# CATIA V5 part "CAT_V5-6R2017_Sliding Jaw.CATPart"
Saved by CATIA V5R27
Part number: Sliding Jaw
Bounding box of the stored display mesh (mm): x -32 to 32, y -16 to 16, z -9 to 36
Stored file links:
  E:\_Deepak\2017_Deepak\CATIA\Resources\Tutorial Files\Tutorials\c16_catia_v5_6r2016_tut\Bench vice\CAT_V5-6R2016_Sliding Jaw.CATPart
  C:\Program Files\Dassault Systemes\B09\intel_a\reffiles\standard\MetricThickPitch.txt
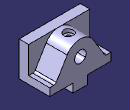
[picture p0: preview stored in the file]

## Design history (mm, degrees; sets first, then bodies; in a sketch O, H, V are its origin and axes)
Body1 (main body)
  Sketch1 on xy-plane, origin (0, 0, 0), H (1, 0, 0), V (0, 1, 0)
    line L1 (-32, -16) -> (32, -16)
    line L2 (32, -16) -> (32, 16)
    line L3 (32, 16) -> (-32, 16)
    line L4 (-32, 16) -> (-32, -16)
    distance H L1 = 16
    distance V L4 = 32
    length L4 = 32
    length L1 = 64
    horizontal: L1 H, L3 H
    vertical: L2 V, L4 V
  Pad1: profile Sketch1, direction (0, 0, 1), length 8
  Sketch2 on face of Pad1, origin (0, -16, 0), H (1, 0, 0), V (0, 0, 1)
    point P1 (-32, 0)
    line L1 (-32, 0) -> (32, 0)
    line L2 (32, 0) -> (32, 36)
    line L3 (32, 36) -> (-32, 36)
    line L4 (-32, 36) -> (-32, 0)
    reference projected line E1 (32, 0) -> (32, 8) from edge of Pad1
    reference projected line E2 (-32, 8) -> (-32, 0) from edge of Pad1
    length L2 = 36
    coincidence: P1 H, L2 E1, L4 E2
    horizontal: L1 H, L3 H
    vertical: L2 V, L4 V
  Pad2: profile Sketch2, direction (0, 1, 0), length 10
  Sketch3 on face of Pad1, origin (0, 16, 0), H (-1, 0, 0), V (0, 0, 1)
    arc A1 centre (0, 20) radius 16 from (13.6777, 28.3018) to (-13.6777, 28.3018) ccw
    point P1 (0, 20)
    reference projected line E1 (-32, 36) -> (32, 36) from edge of Pad2
    line L1 (-26, 8) -> (-13.6777, 28.3018)
    point P2 (-26, 8)
    line L2 (13.6777, 28.3018) -> (26, 8)
    point P3 (26, 8)
    reference projected line E2 (32, 8) -> (-32, 8) from edge of Pad1
    reference projected line E3 (32, 8) -> (-32, 8) from edge of Pad1
    line L3 (-26, 8) -> (26, 8)
    radius A1 = 16
    length L3 = 52
    distance V P3 = 26
    coincidence: P1 V, E2 P2, E3 P3
    tangency: A1 E1, L2 A1, L1 A1
    horizontal: L3 H
  Pad3: profile Sketch3, direction (0, -1, 0), up to the existing solid (limit type 2)
  Fillet1: radius 3, on 2 edges
  Sketch4 on face of Pad1, origin (-2.6964, 16, 22.8197), H (1, 0, 0), V (0, 0, -1)
    point P1 (2.6964, 2.8197)
    reference projected arc E1 centre (2.6964, 2.8197) radius 16 from (-10.9814, -5.4821) to (16.3741, -5.4821) ccw from edge of Pad3
    concentricity: P1 E1
  Hole1: placed by Sketch4, at (0, 16, 20) direction (0, -1, 0), diameter 12, depth 22, V-bottom angle 120
  Sketch5 on face of Pad1, origin (0, 16, 0), H (-1, 0, 0), V (0, 0, 1)
    point P1 (-7.75, 0)
    line L1 (-7.75, 0) -> (7.75, 0)
    line L2 (7.75, 0) -> (7.75, -9)
    line L3 (7.75, -9) -> (-7.75, -9)
    line L4 (-7.75, -9) -> (-7.75, 0)
    distance V L2 = 7.75
    length L3 = 15.5
    length L4 = 9
    coincidence: P1 H
    horizontal: L1 H, L3 H
    vertical: L2 V, L4 V
  Pad4: profile Sketch5, direction (0, -1, 0), length 32
  Sketch6 on face of Pad4, origin (-0.598, -1.2346, -9), H (1, 0, 0), V (0, -1, 0)
    point P1 (0.598, -9.2346)
    reference projected line E1 (8.348, -17.2346) -> (-7.152, -17.2346) from edge of Pad4
    reference projected line E2 (8.348, 14.7654) -> (8.348, -17.2346) from edge of Pad4
    distance P1 E1 = 8
    distance P1 E2 = 7.75
  Hole2: placed by Sketch6, at (0, 8, -9) direction (0, 0, 1), diameter 5, depth 16, V-bottom angle 120, threaded, thread diameter 6, thread depth 16, pitch 1
  RectPattern1: of Hole2, direction 1 instances 2, spacing 16, along edge of Pad4 reversed
  Sketch7 on face of Pad2, origin (-19.6018, -13.7351, 36), H (1, 0, 0), V (0, 1, 0)
    point P1 (19.6018, 17.7351)
    reference intersected line E1 through (19.6018, 0) direction (0, 1) from yz-plane
    reference projected line E2 (51.6018, -2.2649) -> (-12.3982, -2.2649) from edge of Pad2
    distance P1 E2 = 20
    coincidence: E1 P1
  Hole3: placed by Sketch7, at (0, 4, 36) direction (0, 0, -1), diameter 5, depth 16, V-bottom angle 120, counterbore diameter 10, counterbore depth 4, threaded, thread diameter 6, thread depth 11, pitch 1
